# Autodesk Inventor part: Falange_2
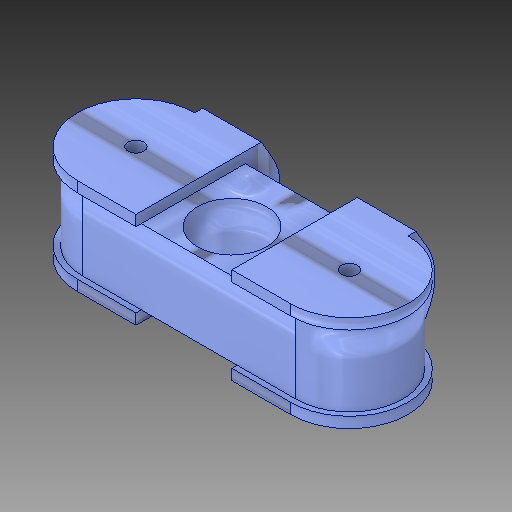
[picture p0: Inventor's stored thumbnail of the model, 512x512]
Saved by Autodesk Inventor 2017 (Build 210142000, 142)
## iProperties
Created: 2017-02
Part Number: Falange_2
Material: Generic
Document SubType Name: Modeling
Designer: alez_
Density: 1 g/cm^3
Appearance: 4in Square - Light Blue
Author: alez_
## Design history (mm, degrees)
sketch "Sketch1"
  geometry: L1 (0, 0)-(-31, 0); L2 (-31, 0)-(-31, -13.5); L3 (-31, -13.5)-(0, -13.5); L4 (0, -13.5)-(0, 0)
  constraints: 8 end point, 3 perpendicular, 1 horizontal
  dimensions: "d0" = 31 distance of L1.start L1.end; "d1" = 13.5 distance of L1.end L2.end
extrude "Extrusion1" new body sketch "Sketch1" distance "d2" = 9; taper "d3" = 0 deg
sketch "Sketch2"
  geometry: L1 (31, 0)-(31, 13.5) reference; L2 (20, 0)-(20, 13.5); L3 (11, 13.5)-(11, 0); L4 (11, 0)-(20, 0); L5 (11, 13.5)-(20, 13.5); 1 further point
  constraints: 8 end point, 1 parallel
  dimensions: "d4" = 11 distance of L1.start L2.start; "d5" = 11 distance of point (0, 13.5) L3.start
extrude "Extrusion2" cut sketch "Sketch2" distance "d6" = 1; taper "d7" = 0 deg
sketch "Sketch3"
  geometry: L1 (31, 0)-(31, -13.5) reference; L2 (0, 0)-(31, 0) reference; L3 (31, -13.5)-(20, -13.5) reference; L4 (20, 0)-(20, -13.5); L5 (11, -13.5)-(20, -13.5) reference; L6 (20, -13.5)-(11, -13.5); L7 (0, 0)-(11, 0) reference; L8 (11, -13.5)-(11, 0); L9 (11, 0)-(20, 0)
  constraints: 8 end point, 1 collinear, 1 perpendicular, 1 point on line
  dimensions: "d8" = 11 distance of L1.start L4.start
extrude "Extrusion3" cut sketch "Sketch3" distance "d9" = 1; taper "d10" = 0 deg
sketch "Sketch5"
  geometry: L1 (11, 13.5)-(0, 13.5) reference; L2 (11, 13.5)-(20, 13.5) reference; L3 (20, 0)-(11, 0) reference; L4 (15.5, 0)-(15.5, 4.5); C1 r 3.25 at (15.5, 4.5); 1 further point
  constraints: 2 end point, 1 centre point, 1 coincident, 1 midpoint, 1 vertical
  dimensions: "d12" = 6.5 diameter of C1; "d63" = 4.5 distance of L4.start L4.end
extrude "Extrusion4" cut sketch "Sketch5" distance "d13" = 7; taper "d14" = 0 deg
sketch "Sketch8"
  geometry: L1 (0, 0)-(11, 0) reference; L2 (20, 0)-(31, 0) reference; L3 (31, 0)-(31, 13.5) reference; C1 r 0.75 at (5.5, 5.5); C2 r 0.75 at (25.5, 5.5)
  constraints: 2 centre point
  dimensions: "d52" = 1.5 diameter of C1; "d53" = 1.5 diameter of C2
extrude "Extrusion7" cut sketch "Sketch8" distance "d40" = 9; taper "d41" = 0 deg
sketch "Sketch11"
  geometry: L1 (0, 13.5)-(0, 0) reference; L2 (31, 0)-(31, 13.5) reference; L3 (25.5, 11)-(25.5, 13.5); L4 (25.5, 13.5)-(31, 13.5); L5 (31, 13.5)-(31, 5.5); L6 (31, 5.5)-(31, 0); L7 (31, 0)-(25.5, 0); L8 (5.5, 11)-(5.5, 13.5); L9 (5.5, 13.5)-(0, 13.5); L10 (0, 13.5)-(0, 5.5); L11 (0, 5.5)-(0, 0); L12 (0, 0)-(5.5, 0); C1 r 0.75 at (5.5, 5.5) reference; C2 r 0.75 at (25.5, 5.5) reference; A1 r 5.5 centre (5.5, 5.5) between (5.5, 11) and (5.5, 0); A2 r 5.5 centre (25.5, 5.5) between (25.5, 0) and (25.5, 11)
  constraints: 20 end point, 6 point on circle, 3 point on line, 3 tangent, 2 centre point, 2 coincident, 2 collinear, 2 perpendicular
extrude "Extrusion8" cut sketch "Sketch11" distance "d54" = 9; taper "d55" = 0 deg
sketch "Sketch14"
  geometry: L1 (20, 0)-(11, 0) reference; L2 (15.5, 0)-(15.5, 0.5); L3 (31.5, 0.5)-(31.5, 0); L4 (31.5, 0)-(-0.5, 0); L5 (-0.5, 0)-(-0.5, 0.5); L6 (-0.5, 0.5)-(31.5, 0.5); 1 further point
  constraints: 10 end point, 1 midpoint, 1 perpendicular, 1 vertical
  dimensions: "d57" = 0.5 distance of L2.start L2.end; "d58" = 16 distance of L2.end L3.start; "d59" = 32 distance of L3.end L4.end; "d60" = 0.5 distance of L4.end L5.end
extrude "Extrusion9" cut sketch "Sketch14" distance "d61" = 7; taper "d62" = 0 deg
sketch "Sketch15"
  geometry: L1 (15.5, 7.75)-(15.5, 10.25); L2 (15.5, 10.25)-(20, 10.25); L3 (20, 13.5)-(20, 0.5) reference; L4 (25.5, 13.5)-(20, 13.5) reference; L5 (20, 10.25)-(20, 13.5); L6 (11, 0.5)-(11, 13.5) reference; L7 (20, 13.5)-(11, 13.5); L8 (11, 13.5)-(11, 10.25); L9 (11, 10.25)-(15.5, 10.25); 2 further points
  constraints: 12 end point, 3 perpendicular, 3 point on line, 1 collinear, 1 vertical, 1 vertical alignment, 1 other
  dimensions: "d64" = 2.5 distance of L1.start L1.end
extrude "Extrusion10" cut sketch "Sketch15" distance "d65" = 7; taper "d66" = 0 deg
sketch "Sketch17"
  geometry: L1 (2.5, 9)-(2.5, 0) reference; L2 (0, 9)-(2.5, 9) reference; L3 (2.5, 7.652)-(2.5, 9); L4 (2.5, 9)-(-11, 9) reference; L5 (2.5, 9)-(2.5, 6); L6 (2.5, 9)-(2.5, 0) reference; L7 (2.5, 6)-(1, 6); C1 r 0.75 at (1, 6); 2 further points
  constraints: 6 end point, 2 point on line, 1 centre point, 1 coincident, 1 horizontal, 1 perpendicular
  dimensions: "d98" = 3 distance of L1.start L5.end; "d99" = 1.5 distance of L5.end L7.end; "d109" = 1.5 diameter of C1
extrude "Extrusion11" cut sketch "Sketch17" distance "d70" = 5.5; taper "d71" = 0 deg
sketch "Sketch19"
  geometry: L1 (5.5, -13.5)-(5.5, -11) reference; L2 (5.5, 0)-(11, 0) reference; L3 (5.5, -11)-(5.5, 0); L4 (25.5, -11)-(25.5, 0); C1 r 0.75 at (25.5, -5.5) reference; C2 r 0.75 at (5.5, -5.5) reference; A1 r 5 centre (25.5, -5.5) between (25.5, -10.5) and (25.5, -0.5); A2 r 5.5 centre (25.5, -5.5) between (25.5, -11) and (25.5, 0) reference; A3 r 5.5 centre (25.5, -5.5) between (25.5, -11) and (25.5, 0); A4 r 5 centre (5.5, -5.5) between (5.5, -0.5) and (5.5, -10.5); A5 r 5.5 centre (5.5, -5.5) between (5.5, 0) and (5.5, -11); 2 further points
  constraints: 8 point on circle, 4 centre point, 4 coincident, 4 end point, 4 point on line, 2 vertical
  dimensions: "d77" = 10 diameter of A1; "d78" = 10 diameter of A4
extrude "Extrusion13" cut sketch "Sketch19" distance "d79" = 7; taper "d80" = 0 deg
sketch "Sketch22"
  geometry: L1 (0, 0)-(0, -1) reference; L2 (-11, 0)-(2.5, 0) reference; L3 (2.5, 0)-(2.5, -9) reference; L4 (2.5, 0)-(2.5, -3); L5 (0.75, 0)-(2.5, -3); L6 (0, -8)-(0, -9) reference; L7 (0, -9)-(2.5, -9) reference; L8 (2.5, -9)-(2.5, -6); L9 (2.5, -6)-(0.75, -9); L10 (0.75, 0)-(2.5, 0); L11 (0.75, -9)-(2.5, -9); 1 further point
  constraints: 12 end point, 4 point on line, 2 collinear
  dimensions: "d81" = 0.75 distance of L1.start L5.start; "d82" = 3 distance of L2.end L4.end; "d83" = 0.75 distance of L6.end L9.end; "d84" = 3 distance of L3.end L8.end
extrude "Extrusion14" cut sketch "Sketch22" distance "d85" = 20; taper "d86" = 0 deg
fillet "Fillet2" dims "d88" = 5
sketch "Sketch32"
  geometry: L1 (-2.5, 4.648)-(-2.5, 4.352) reference; L2 (-2.5, 4.5)-(-1, 4.5); C1 r 0.75 at (-1, 4.5); 1 further point
  constraints: 2 end point, 1 centre point, 1 coincident, 1 horizontal, 1 midpoint
  dimensions: "d110" = 1.5 distance of L2.start L2.end
extrude "Extrusion17" cut sketch "Sketch32" distance "d111" = 5.5; taper "d112" = 0 deg
body "Solid1"
